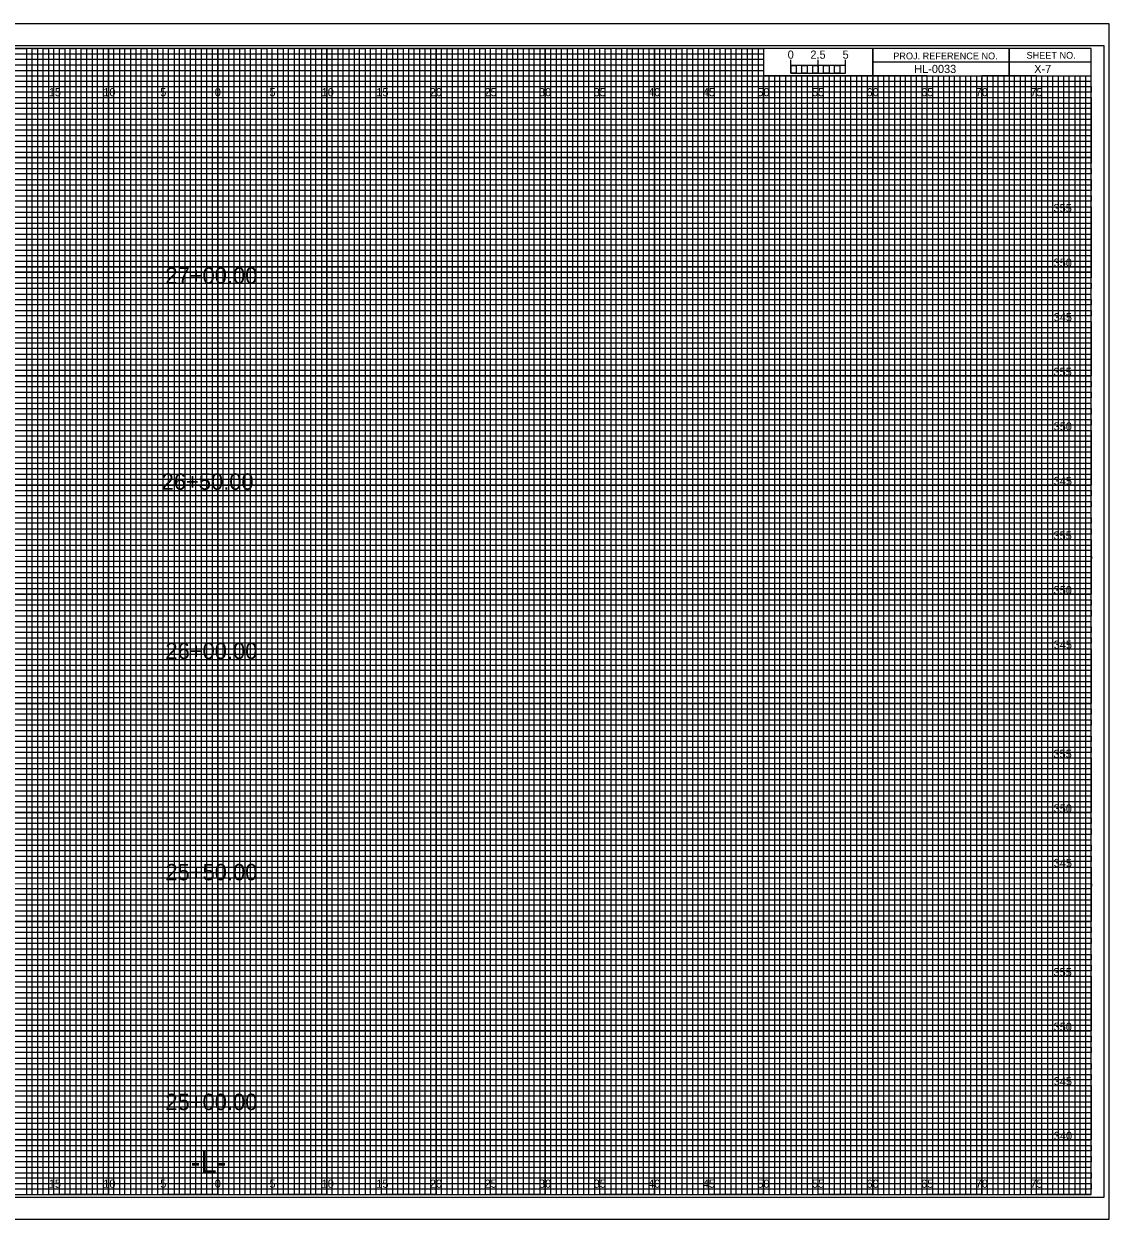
# Model space of a CAD drawing. Extents: x -40 to 162, y 548 to 657.
# Drawn here: x 62.2 to 161.7, y 547.8 to 657.2 of the extents above; entities that cross this region are included whole.
import ezdxf

# ---------------------------------------------------------------- set-up
doc = ezdxf.new("R2010")
doc.units = 0
for name, color, linetype in [('Prop XS Alignment Label', 7, 'Continuous'), ('Prop XS Bar Scale Labels', 7, 'Continuous'), ('Prop XS Elevation Labels', 7, 'Continuous'), ('Prop XS Offset Labels', 7, 'Continuous'), ('Prop XS Project Number', 7, 'Continuous'), ('Prop XS Sheet Number', 7, 'Continuous'), ('Prop XS Station Labels', 7, 'Continuous'), ('Sheet Cross Section CELL', 7, 'Continuous'), ('Sheet Cross Section Grid Major CELL', 7, 'Continuous'), ('Sheet Cross Section Grid Middle CELL', 7, 'Continuous'), ('Sheet Cross Section Grid Minor 1 CELL', 7, 'Continuous'), ('Sheet Cross Section Grid Minor 2 CELL', 7, 'Continuous'), ('Sheet Cross Section Scale CELL', 7, 'Continuous'), ('Sheet Cutting Line CELL', 7, 'Continuous'), ('Sheet DOT Grid CELL', 7, 'Continuous'), ('Sheet Plot Border Inside CELL', 7, 'Continuous'), ('Sheet Plot Border Outside CELL', 7, 'Continuous')]:
    doc.layers.add(name, color=color, linetype=linetype)

msp = doc.modelspace()

# ---------------------------------------------------------------- linework, layer by layer
at = {"layer": 'Sheet Cross Section CELL'}
for p, q in [((152.5, 655), (152.5, 652.5)), ((152.5, 652.5), (152.5, 655)), ((160, 653.75), (140, 653.75)), ((140, 653.75), (140, 652.5)), ((140, 652.5), (160, 652.5))]:
    msp.add_line(p, q, dxfattribs=at)
for points in [[(160, 655), (0, 655), (0, 550), (160, 550)], [(140, 655), (130, 655), (130, 652.51), (140, 652.51)], [(160, 655), (140, 655), (140, 652.5), (160, 652.5)]]:
    msp.add_lwpolyline(points, close=True, dxfattribs=at)
at = {"layer": 'Sheet Cross Section Grid Major CELL'}
for p, q in [((65, 655), (60, 655)), ((65, 550), (65, 655)), ((75, 655), (70, 655)), ((70, 655), (70, 550)), ((75, 550), (75, 655)), ((85, 655), (80, 655)), ((80, 655), (80, 550)), ((85, 550), (85, 655)), ((95, 655), (90, 655)), ((90, 655), (90, 550)), ((95, 550), (95, 655)), ((105, 655), (100, 655)), ((100, 655), (100, 550)), ((105, 550), (105, 655)), ((115, 655), (110, 655)), ((110, 655), (110, 550)), ((115, 550), (115, 655)), ((125, 655), (120, 655)), ((120, 655), (120, 550)), ((125, 550), (125, 655)), ((130, 655), (130, 550)), ((135, 550), (135, 652.5)), ((145, 652.5), (140, 652.5)), ((140, 652.5), (140, 550)), ((145, 550), (145, 652.5)), ((155, 652.5), (150, 652.5)), ((150, 652.5), (150, 550)), ((155, 550), (155, 652.5)), ((70, 550), (65, 550)), ((80, 550), (75, 550)), ((90, 550), (85, 550)), ((100, 550), (95, 550)), ((110, 550), (105, 550)), ((120, 550), (115, 550)), ((130, 550), (125, 550)), ((140, 550), (135, 550)), ((150, 550), (145, 550)), ((160, 550), (155, 550)), ((160, 550), (160, 550))]:
    msp.add_line(p, q, dxfattribs=at)
for points in [[(0, 650), (160, 650), (160, 645), (35, 645)], [(0, 640), (160, 640), (160, 635), (0, 635)], [(0, 630), (160, 630), (160, 625), (0, 625)], [(0, 620), (160, 620), (160, 615), (0, 615)], [(0, 610), (160, 610), (160, 605), (0, 605)], [(0, 600), (160, 600), (160, 595), (0, 595)], [(0, 590), (160, 590), (160, 585), (0, 585)], [(0, 580), (160, 580), (160, 575), (0, 575)], [(0, 570), (160, 570), (160, 565), (0, 565)], [(0, 560), (160, 560), (160, 555), (0, 555)]]:
    msp.add_lwpolyline(points, dxfattribs=at)
at = {"layer": 'Sheet Cross Section Grid Middle CELL'}
for points in [[(57.5, 655), (62.5, 655), (62.5, 550), (67.5, 550), (67.5, 655), (72.5, 655), (72.5, 550), (77.5, 550), (77.5, 655), (82.5, 655), (82.5, 550), (87.5, 550), (87.5, 655), (92.5, 655), (92.5, 550), (97.5, 550), (97.5, 655), (102.5, 655), (102.5, 550), (107.5, 550), (107.5, 655), (112.5, 655), (112.5, 550), (117.5, 550), (117.5, 655), (122.5, 655), (122.5, 550), (127.5, 550), (127.5, 655), (129.97, 655), (130, 655), (130, 652.5), (132.5, 652.5), (132.5, 550), (137.5, 550), (137.5, 652.5), (142.5, 652.5), (142.5, 550), (147.5, 550), (147.5, 652.5), (152.5, 652.5), (152.5, 550), (157.5, 550), (157.5, 652.5)], [(0, 652.5), (137.5, 652.5)], [(35, 642.5), (160, 642.5), (160, 647.5), (35, 647.5)], [(0, 632.5), (160, 632.5), (160, 637.5), (0, 637.5)], [(0, 622.5), (160, 622.5), (160, 627.5), (0, 627.5)], [(0, 612.5), (160, 612.5), (160, 617.5), (0, 617.5)], [(0, 602.5), (160, 602.5), (160, 607.5), (0, 607.5)], [(0, 592.5), (160, 592.5), (160, 597.5), (0, 597.5)], [(0, 582.5), (160, 582.5), (160, 587.5), (0, 587.5)], [(0, 572.5), (160, 572.5), (160, 577.5), (0, 577.5)], [(0, 562.5), (160, 562.5), (160, 567.5), (0, 567.5)], [(0, 552.5), (160, 552.5), (160, 557.5), (0, 557.5)]]:
    msp.add_lwpolyline(points, dxfattribs=at)
at = {"layer": 'Sheet Cross Section Grid Minor 1 CELL'}
for p, q in [((0, 654.5), (130, 654.5)), ((130, 653.99), (0, 653.99)), ((130, 654.5), (130, 653.99)), ((0, 653.5), (130, 653.5)), ((130, 652.95), (0, 652.95)), ((130, 653.5), (130, 652.95)), ((0, 652), (160, 652))]:
    msp.add_line(p, q, dxfattribs=at)
for points in [[(0, 651.5), (135, 651.5), (160, 651.5), (160, 651), (0, 651)], [(0, 650.5), (160, 650.5), (160, 649.5), (0, 649.5)], [(0, 649), (160, 649), (160, 648.5), (0, 648.49)], [(0, 648), (160, 648), (160, 647), (35, 647)], [(35, 646.5), (160, 646.5), (160, 646), (35, 646)], [(35, 645.5), (160, 645.5), (160, 644.5), (35, 644.5)], [(35, 644), (160, 644), (160, 643.5), (35, 643.5)], [(35, 643), (160, 643), (160, 642), (0, 642)], [(0, 641.5), (160, 641.5), (160, 641), (0, 641)], [(0, 640.5), (160, 640.5), (160, 639.5), (0, 639.5)], [(0, 639), (160, 639), (160, 638.5), (0, 638.5)], [(0, 638), (160, 638), (160, 636.98), (160, 636.5), (160, 636), (0, 636)], [(0, 637), (160, 637), (160, 636.5), (0, 636.5)], [(0, 635.5), (160, 635.5), (160, 634.5), (0, 634.51)], [(0, 634.51), (160, 634.5), (160, 634), (0, 634)], [(0, 633.5), (160, 633.5), (160, 633), (0, 633)], [(0, 632), (160, 632), (160, 631.5), (0, 631.5)], [(0, 631), (160, 631), (160, 630.5), (0, 630.5)], [(-0.04, 629.45), (160, 629.45), (160, 628.94), (-0.04, 628.94)], [(0, 628.5), (160, 628.5), (160, 628), (0, 628)], [(0, 627), (160, 627), (160, 626.5), (0, 626.5)], [(0, 626), (160, 626), (160, 625.5), (0, 625.5)], [(0, 624.5), (160, 624.5), (160, 624), (0, 624)], [(0, 623.5), (160, 623.5), (160, 623), (0, 623)], [(0, 622), (160, 622), (160, 621.5), (0, 621.5)], [(0, 621), (160, 621), (160, 620.5), (0, 620.5)], [(0, 619.5), (160, 619.5), (160, 618.99), (0, 619)], [(0, 618.5), (160, 618.5), (160, 618), (0, 618)], [(0, 617), (160, 617), (160, 616.5), (0, 616.5)], [(0, 616), (160, 616), (160, 615.5), (0, 615.5)], [(0, 614.5), (160, 614.5), (160, 614), (0, 614)], [(0, 613.5), (160, 613.5), (160, 613), (0, 613)], [(0, 612), (160, 612), (160, 611.5), (0, 611.5)], [(0, 611), (160, 611), (160, 610.5), (0, 610.5)], [(0, 609.5), (160, 609.5), (160, 609), (0, 609)], [(0, 608.5), (160.03, 608.46), (160, 608), (0, 608)], [(0, 607), (160, 607), (160, 606.5), (0, 606.5)], [(0, 606), (160, 606), (160, 605.5), (0, 605.5)], [(0, 604.5), (160, 604.5), (160, 604), (0, 604)], [(0, 603.5), (160, 603.5), (160, 603), (0, 603)], [(0, 602), (160, 602), (160, 601.5), (0, 601.5)], [(0, 601), (160, 601), (160, 600.5), (0, 600.5)], [(0, 599.5), (160, 599.5), (160, 599), (0, 599)], [(0, 598.5), (160, 598.5), (160, 598), (0, 598)], [(0, 597), (160, 597), (160, 596.5), (0, 596.5)], [(0, 596), (160, 596), (160, 595.5), (0, 595.5)], [(0, 594.5), (160, 594.5), (160, 594), (0, 594)], [(0, 593.5), (160, 593.5), (160, 593), (0, 593)], [(0, 592), (160, 592), (160, 591.5), (0, 591.5)], [(0, 591), (160, 591), (160, 590.5), (0, 590.5)], [(0, 589.5), (160, 589.5), (160, 588.99), (0, 589)], [(0, 588.5), (160, 588.5), (160, 588), (0, 588)], [(0, 587), (160, 587), (160, 586.5), (0, 586.5)], [(0, 586), (160, 586), (160, 585.5), (0, 585.5)], [(0, 584.5), (160, 584.5), (160, 584), (0, 584)], [(0, 583.5), (160, 583.5), (160, 583), (0, 583)], [(0, 582), (160, 582), (160, 581.5), (0, 581.5)], [(0, 581), (160, 581), (160, 580.5), (0, 580.5)], [(0, 579.5), (160, 579.5), (160, 579), (0, 579)], [(0, 578.5), (160.03, 578.46), (160, 578), (0, 578)], [(0, 577), (160, 577), (160, 576.5), (0, 576.5)], [(0, 576), (160, 576), (160, 575.5), (0, 575.5)], [(0, 574.5), (160, 574.5), (160, 574), (0, 574)], [(0, 573.5), (160, 573.5), (160, 573), (0, 573)], [(0, 572), (160, 572), (160, 571.5), (0, 571.5)], [(0, 571), (160, 571), (160, 570.5), (0, 570.5)], [(0, 569.5), (160, 569.5), (160, 569), (0, 569)], [(0, 568.5), (160, 568.5), (160, 568), (0, 568)], [(0, 567), (160, 567), (160, 566.5), (0, 566.5)], [(0, 566), (160, 566), (160, 565.5), (0, 565.5)], [(0, 564.5), (160, 564.5), (160, 564), (0, 564)], [(0, 563.5), (160, 563.5), (160, 563), (0, 563)], [(0, 562), (160, 562), (160, 561.5), (0, 561.5)], [(0, 561), (160, 561), (160, 560.5), (0, 560.5)], [(0, 559.5), (160, 559.5), (160, 559), (0, 559)], [(0, 558.5), (160, 558.5), (160, 558), (0, 558)], [(0, 557), (160, 557), (160, 556.5), (0, 556.5)], [(0, 556), (160, 556), (160, 555.5), (0, 555.5)], [(0, 554.5), (160, 554.5), (160, 554), (0, 554)], [(0, 553.5), (160, 553.5), (160, 553), (0, 553)], [(0, 552), (160, 552), (160, 551.5), (0, 551.5)], [(0, 551), (160, 551), (160, 550.5), (0, 550.5)]]:
    msp.add_lwpolyline(points, dxfattribs=at)
at = {"layer": 'Sheet Cross Section Grid Minor 2 CELL'}
for p, q in [((133.5, 652.5), (133, 652.5)), ((133, 652.5), (133, 550)), ((133.5, 550), (133.5, 652.5)), ((134.5, 652.5), (134, 652.5)), ((134, 652.5), (134, 550)), ((134.5, 550), (134.5, 652.5)), ((133, 550), (132.5, 550)), ((134, 550), (133.5, 550))]:
    msp.add_line(p, q, dxfattribs=at)
for points in [[(62.5, 550), (63, 550), (63, 655), (63.5, 655), (63.5, 550)], [(63.5, 550), (64, 550), (64, 655), (64.5, 655), (64.5, 550)], [(65, 550), (65.5, 550), (65.5, 655), (66, 655), (66, 550)], [(66, 550), (66.5, 550), (66.5, 655), (67, 655), (67, 550)], [(67.5, 550), (68, 550), (68, 655), (68.5, 655), (68.5, 550)], [(68.5, 550), (69, 550), (69, 655), (69.5, 655), (69.5, 550)], [(70, 550), (70.5, 550), (70.5, 655), (71, 655), (71, 550)], [(71, 550), (71.5, 550), (71.5, 655), (72, 655), (72, 550)], [(72.5, 550), (73, 550), (73, 655), (73.5, 655), (73.5, 550)], [(73.5, 550), (74, 550), (74, 655), (74.5, 655), (74.5, 550)], [(75, 550), (75.5, 550), (75.5, 655), (76, 655), (76, 550)], [(76, 550), (76.5, 550), (76.5, 655), (77, 655), (77, 550)], [(77.5, 550), (78, 550), (78, 655), (78.5, 655), (78.5, 550)], [(78.5, 550), (79, 550), (79, 655), (79.5, 655), (79.5, 550)], [(80, 550), (80.5, 550), (80.5, 655), (81, 655), (81, 550)], [(81, 550), (81.5, 550), (81.5, 655), (82, 655), (82, 550)], [(82.5, 550), (83, 550), (83, 655), (83.5, 655), (83.5, 550)], [(83.5, 550), (84, 550), (84, 655), (84.5, 655), (84.5, 550)], [(85, 550), (85.5, 550), (85.5, 655), (86, 655), (86, 550)], [(86, 550), (86.5, 550), (86.5, 655), (87, 655), (87, 550)], [(87.5, 550), (88, 550), (88, 655), (88.5, 655), (88.5, 550)], [(88.5, 550), (89, 550), (89, 655), (89.5, 655), (89.5, 550)], [(90, 550), (90.5, 550), (90.5, 655), (91, 655), (91, 550)], [(91, 550), (91.5, 550), (91.5, 655), (92, 655), (92, 550)], [(92.5, 550), (93, 550), (93, 655), (93.5, 655), (93.5, 550)], [(93.5, 550), (94, 550), (94, 655), (94.5, 655), (94.5, 550)], [(95, 550), (95.5, 550), (95.5, 655), (96, 655), (96, 550)], [(96, 550), (96.5, 550), (96.5, 655), (97, 655), (97, 550)], [(97.5, 550), (98, 550), (98, 655), (98.5, 655), (98.5, 550)], [(98.5, 550), (99, 550), (99, 655), (99.5, 655), (99.5, 550)], [(100, 550), (100.5, 550), (100.5, 655), (101, 655), (101, 550)], [(101, 550), (101.5, 550), (101.5, 655), (102, 655), (102, 550)], [(102.5, 550), (103, 550), (103, 655), (103.5, 655), (103.5, 550)], [(103.5, 550), (104, 550), (104, 655), (104.5, 655), (104.5, 550)], [(105, 550), (105.5, 550), (105.5, 655), (106, 655), (106, 550)], [(106, 550), (106.5, 550), (106.5, 655), (107, 655), (107, 550)], [(107.5, 550), (108, 550), (108, 655), (108.5, 655), (108.5, 550)], [(108.5, 550), (109, 550), (109, 655), (109.5, 655), (109.5, 550)], [(110, 550), (110.5, 550), (110.5, 655), (111, 655), (111, 550)], [(111, 550), (111.5, 550), (111.5, 655), (112, 655), (112, 550)], [(112.5, 550), (113, 550), (113, 655), (113.5, 655), (113.5, 550)], [(113.5, 550), (114, 550), (114, 655), (114.5, 655), (114.5, 550)], [(115, 550), (115.5, 550), (115.5, 655), (116, 655), (116, 550)], [(116, 550), (116.5, 550), (116.5, 655), (117, 655), (117, 550)], [(117.5, 550), (118, 550), (118, 655), (118.5, 655), (118.5, 550)], [(118.5, 550), (119, 550), (119, 655), (119.5, 655), (119.5, 550)], [(120, 550), (120.5, 550), (120.5, 655), (121, 655), (121, 550)], [(121, 550), (121.5, 550), (121.5, 655), (122, 655), (122, 550)], [(122.5, 550), (123, 550), (123, 655), (123.5, 655), (123.5, 550)], [(123.5, 550), (124, 550), (124, 655), (124.5, 655), (124.5, 550)], [(125, 550), (125.5, 550), (125.5, 655), (126, 655), (126, 550)], [(126, 550), (126.5, 550), (126.5, 655), (127, 655), (127, 550)], [(127.5, 550), (128, 550), (128, 655), (128.5, 655), (128.5, 550)], [(128.5, 550), (129, 550), (129, 655), (129.5, 655), (129.5, 550)], [(130, 550), (130.5, 550), (130.5, 652.5), (131.01, 652.5), (131.01, 550)], [(131, 550), (131.5, 550), (131.5, 652.5), (132, 652.5), (132, 550)], [(135, 550), (135.49, 550), (135.49, 652.5), (136, 652.5), (136, 550)], [(136, 550), (136.5, 550), (136.5, 652.5), (137.03, 652.5), (137.03, 550)], [(137.5, 550), (138, 550), (138, 652.5), (138.5, 652.5), (138.5, 550)], [(138.5, 550), (139, 550), (139, 652.5), (139.5, 652.5), (139.5, 550)], [(140, 550), (140.5, 550), (140.5, 652.5), (141, 652.5), (141, 550)], [(141, 550), (141.5, 550), (141.5, 652.5), (142, 652.5), (142, 550)], [(142.5, 550), (143, 550), (143, 652.5), (143.5, 652.5), (143.5, 550)], [(143.5, 550), (144, 550), (144, 652.5), (144.5, 652.5), (144.5, 550)], [(145, 550), (145.5, 550), (145.5, 652.5), (146, 652.5), (146, 550)], [(146, 550), (146.5, 550), (146.5, 652.5), (147, 652.5), (147, 550)], [(147.5, 550), (148, 550), (148, 652.5), (148.5, 652.5), (148.5, 550)], [(148.5, 550), (149, 550), (149, 652.5), (149.5, 652.5), (149.5, 550)], [(150, 550), (150.5, 550), (150.5, 652.5), (151, 652.5), (151, 550)], [(151, 550), (151.5, 550), (151.5, 652.5), (152, 652.5), (152, 550)], [(152.5, 550), (153, 550), (153, 652.5), (153.5, 652.5), (153.5, 550)], [(153.5, 550), (154, 550), (154, 652.5), (154.5, 652.5), (154.5, 550)], [(155, 550), (155.5, 550), (155.5, 652.5), (156, 652.5), (156, 550)], [(156, 550), (156.5, 550), (156.5, 652.5), (157, 652.5), (157, 550)], [(157.5, 550), (158, 550), (158, 652.5), (158.5, 652.5), (158.5, 550)], [(158.5, 550), (159, 550), (159, 652.5), (159.5, 652.5), (159.5, 550)]]:
    msp.add_lwpolyline(points, dxfattribs=at)
at = {"layer": 'Sheet Cross Section Scale CELL'}
for p, q in [((132.5, 652.75), (132.5, 653.95)), ((132.5, 653.45), (132.5, 653.95)), ((135, 652.75), (135, 653.95)), ((137.5, 652.75), (137.5, 653.95)), ((137.5, 653.45), (137.5, 653.95))]:
    msp.add_line(p, q, dxfattribs=at)
for points in [[(137.5, 653.45), (132.5, 653.45), (132.5, 652.75), (137.5, 652.75)], [(132.5, 653.45), (133, 653.45), (133, 652.75), (132.5, 652.75)], [(133.5, 653.45), (134, 653.45), (134, 652.75), (133.5, 652.75)], [(134.5, 653.45), (135, 653.45), (135, 652.75), (134.5, 652.75)], [(135.5, 653.45), (136, 653.45), (136, 652.75), (135.5, 652.75)], [(136.5, 653.45), (137, 653.45), (137, 652.75), (136.5, 652.75)]]:
    msp.add_lwpolyline(points, close=True, dxfattribs=at)
at = {"layer": 'Sheet Cutting Line CELL'}
for p, q in [((161.65, 657.25), (-6.7, 657.25)), ((-6.7, 547.75), (161.65, 547.75))]:
    msp.add_line(p, q, dxfattribs=at)
at = {"layer": 'Sheet DOT Grid CELL'}
for p, q in [((65, 550), (65, 655)), ((70, 550), (70, 655)), ((75, 550), (75, 655)), ((80, 550), (80, 655)), ((85, 550), (85, 655)), ((90, 550), (90, 655)), ((95, 550), (95, 655)), ((100, 550), (100, 655)), ((105, 550), (105, 655)), ((110, 550), (110, 655)), ((115, 550), (115, 655)), ((120, 550), (120, 655)), ((125, 550), (125, 655)), ((130, 550), (130, 652.34)), ((135, 550), (135, 652.34)), ((140, 550), (140, 652.34)), ((145, 550), (145, 652.34)), ((150, 550), (150, 652.34)), ((155, 550), (155, 652.34)), ((0, 650), (160, 650)), ((35, 645), (160, 645)), ((0, 640), (160, 640)), ((0, 635), (160, 635)), ((0, 630), (160, 630)), ((0, 625), (160, 625)), ((0, 620), (160, 620)), ((0, 615), (160, 615)), ((0, 610), (160, 610)), ((0, 605), (160, 605)), ((0, 600), (160, 600)), ((0, 595), (160, 595)), ((0, 590), (160, 590)), ((0, 585), (160, 585)), ((0, 580), (160, 580)), ((0, 575), (160, 575)), ((0, 570), (160, 570)), ((0, 565), (160, 565)), ((0, 560), (160, 560)), ((0, 555), (160, 555))]:
    msp.add_line(p, q, dxfattribs=at)
at = {"layer": 'Sheet Plot Border Inside CELL'}
msp.add_lwpolyline([(-5.4, 549.75), (161.2, 549.75), (161.2, 655.25), (-5.4, 655.25)], close=True, dxfattribs=at)
at = {"layer": 'Sheet Plot Border Outside CELL'}
msp.add_lwpolyline([(-6.7, 547.75), (161.65, 547.75), (161.65, 657.25), (-6.7, 657.25)], close=True, dxfattribs=at)

# ---------------------------------------------------------------- texts
at = {"layer": 'Prop XS Alignment Label'}
msp.add_text('-L-', height=2, dxfattribs=at).set_placement((77.53, 552))
at = {"layer": 'Prop XS Bar Scale Labels'}
for s, p in [('2.5', (134.29, 654.06)), ('5', (137.24, 654.06))]:
    msp.add_text(s, height=0.75, dxfattribs=at).set_placement(p)
at = {"layer": 'Prop XS Elevation Labels'}
for s, p in [('355', (156.56, 640)), ('350', (156.57, 635)), ('345', (156.58, 630)), ('355', (156.56, 625)), ('350', (156.57, 620)), ('345', (156.58, 615)), ('355', (156.56, 610)), ('350', (156.57, 605)), ('345', (156.58, 600)), ('355', (156.56, 590)), ('350', (156.57, 585)), ('345', (156.58, 580)), ('355', (156.56, 570)), ('350', (156.57, 565)), ('345', (156.58, 560)), ('340', (156.59, 555))]:
    msp.add_text(s, height=0.75, dxfattribs=at).set_placement(p)
at = {"layer": 'Prop XS Offset Labels'}
for s, p in [('15', (64.53, 650.62)), ('10', (69.52, 650.62)), ('5', (74.74, 650.62)), ('0', (79.73, 650.62)), ('0', (79.73, 650.62)), ('5', (84.74, 650.62)), ('10', (89.52, 650.62)), ('15', (94.53, 650.62)), ('20', (99.43, 650.62)), ('25', (104.44, 650.62)), ('30', (109.43, 650.62)), ('35', (114.44, 650.62)), ('40', (119.43, 650.62)), ('45', (124.44, 650.62)), ('50', (129.43, 650.62)), ('55', (134.44, 650.62)), ('60', (139.43, 650.62)), ('65', (144.44, 650.62)), ('70', (149.43, 650.62)), ('75', (154.44, 650.62)), ('15', (64.53, 550.62)), ('10', (69.52, 550.62)), ('5', (74.74, 550.62)), ('0', (79.73, 550.62)), ('0', (79.73, 550.62)), ('5', (84.74, 550.62)), ('10', (89.52, 550.62)), ('15', (94.53, 550.62)), ('20', (99.43, 550.62)), ('25', (104.44, 550.62)), ('30', (109.43, 550.62)), ('35', (114.44, 550.62)), ('40', (119.43, 550.62)), ('45', (124.44, 550.62)), ('50', (129.43, 550.62)), ('55', (134.44, 550.62)), ('60', (139.43, 550.62)), ('65', (144.44, 550.62)), ('70', (149.43, 550.62)), ('75', (154.44, 550.62))]:
    msp.add_text(s, height=0.75, dxfattribs=at).set_placement(p)
at = {"layer": 'Prop XS Project Number'}
msp.add_text('HL-0033', height=0.75, dxfattribs=at).set_placement((143.8, 652.75))
at = {"layer": 'Prop XS Sheet Number'}
msp.add_text('X-7', height=0.75, dxfattribs=at).set_placement((154.79, 652.75))
at = {"layer": 'Prop XS Station Labels'}
for s, p in [('27+00.00', (75.21, 633.45)), ('26+50.00', (74.87, 614.57)), ('26+00.00', (75.21, 599.06)), ('25+50.00', (75.21, 578.79)), ('25+00.00', (75.21, 557.74))]:
    msp.add_text(s, height=1.5, dxfattribs=at).set_placement(p)
at = {"layer": 'Sheet Cross Section CELL'}
for s, p in [('PROJ. REFERENCE NO.', (141.88, 654)), ('SHEET NO.', (154.09, 654.06))]:
    msp.add_text(s, height=0.625, dxfattribs=at).set_placement(p)
at = {"layer": 'Sheet Cross Section Scale CELL'}
msp.add_text('0', height=0.75, dxfattribs=at).set_placement((132.21, 654.06))

doc.saveas('drawing.dxf')
